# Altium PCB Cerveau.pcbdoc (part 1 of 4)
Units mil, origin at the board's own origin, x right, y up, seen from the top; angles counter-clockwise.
Board outline 3985.6 x 3546.5 mil, 2 copper layers (Top Layer, Bottom Layer), stack 62.2 mil thick; 170 components, 173 nets, 734 pads, 576 vias.
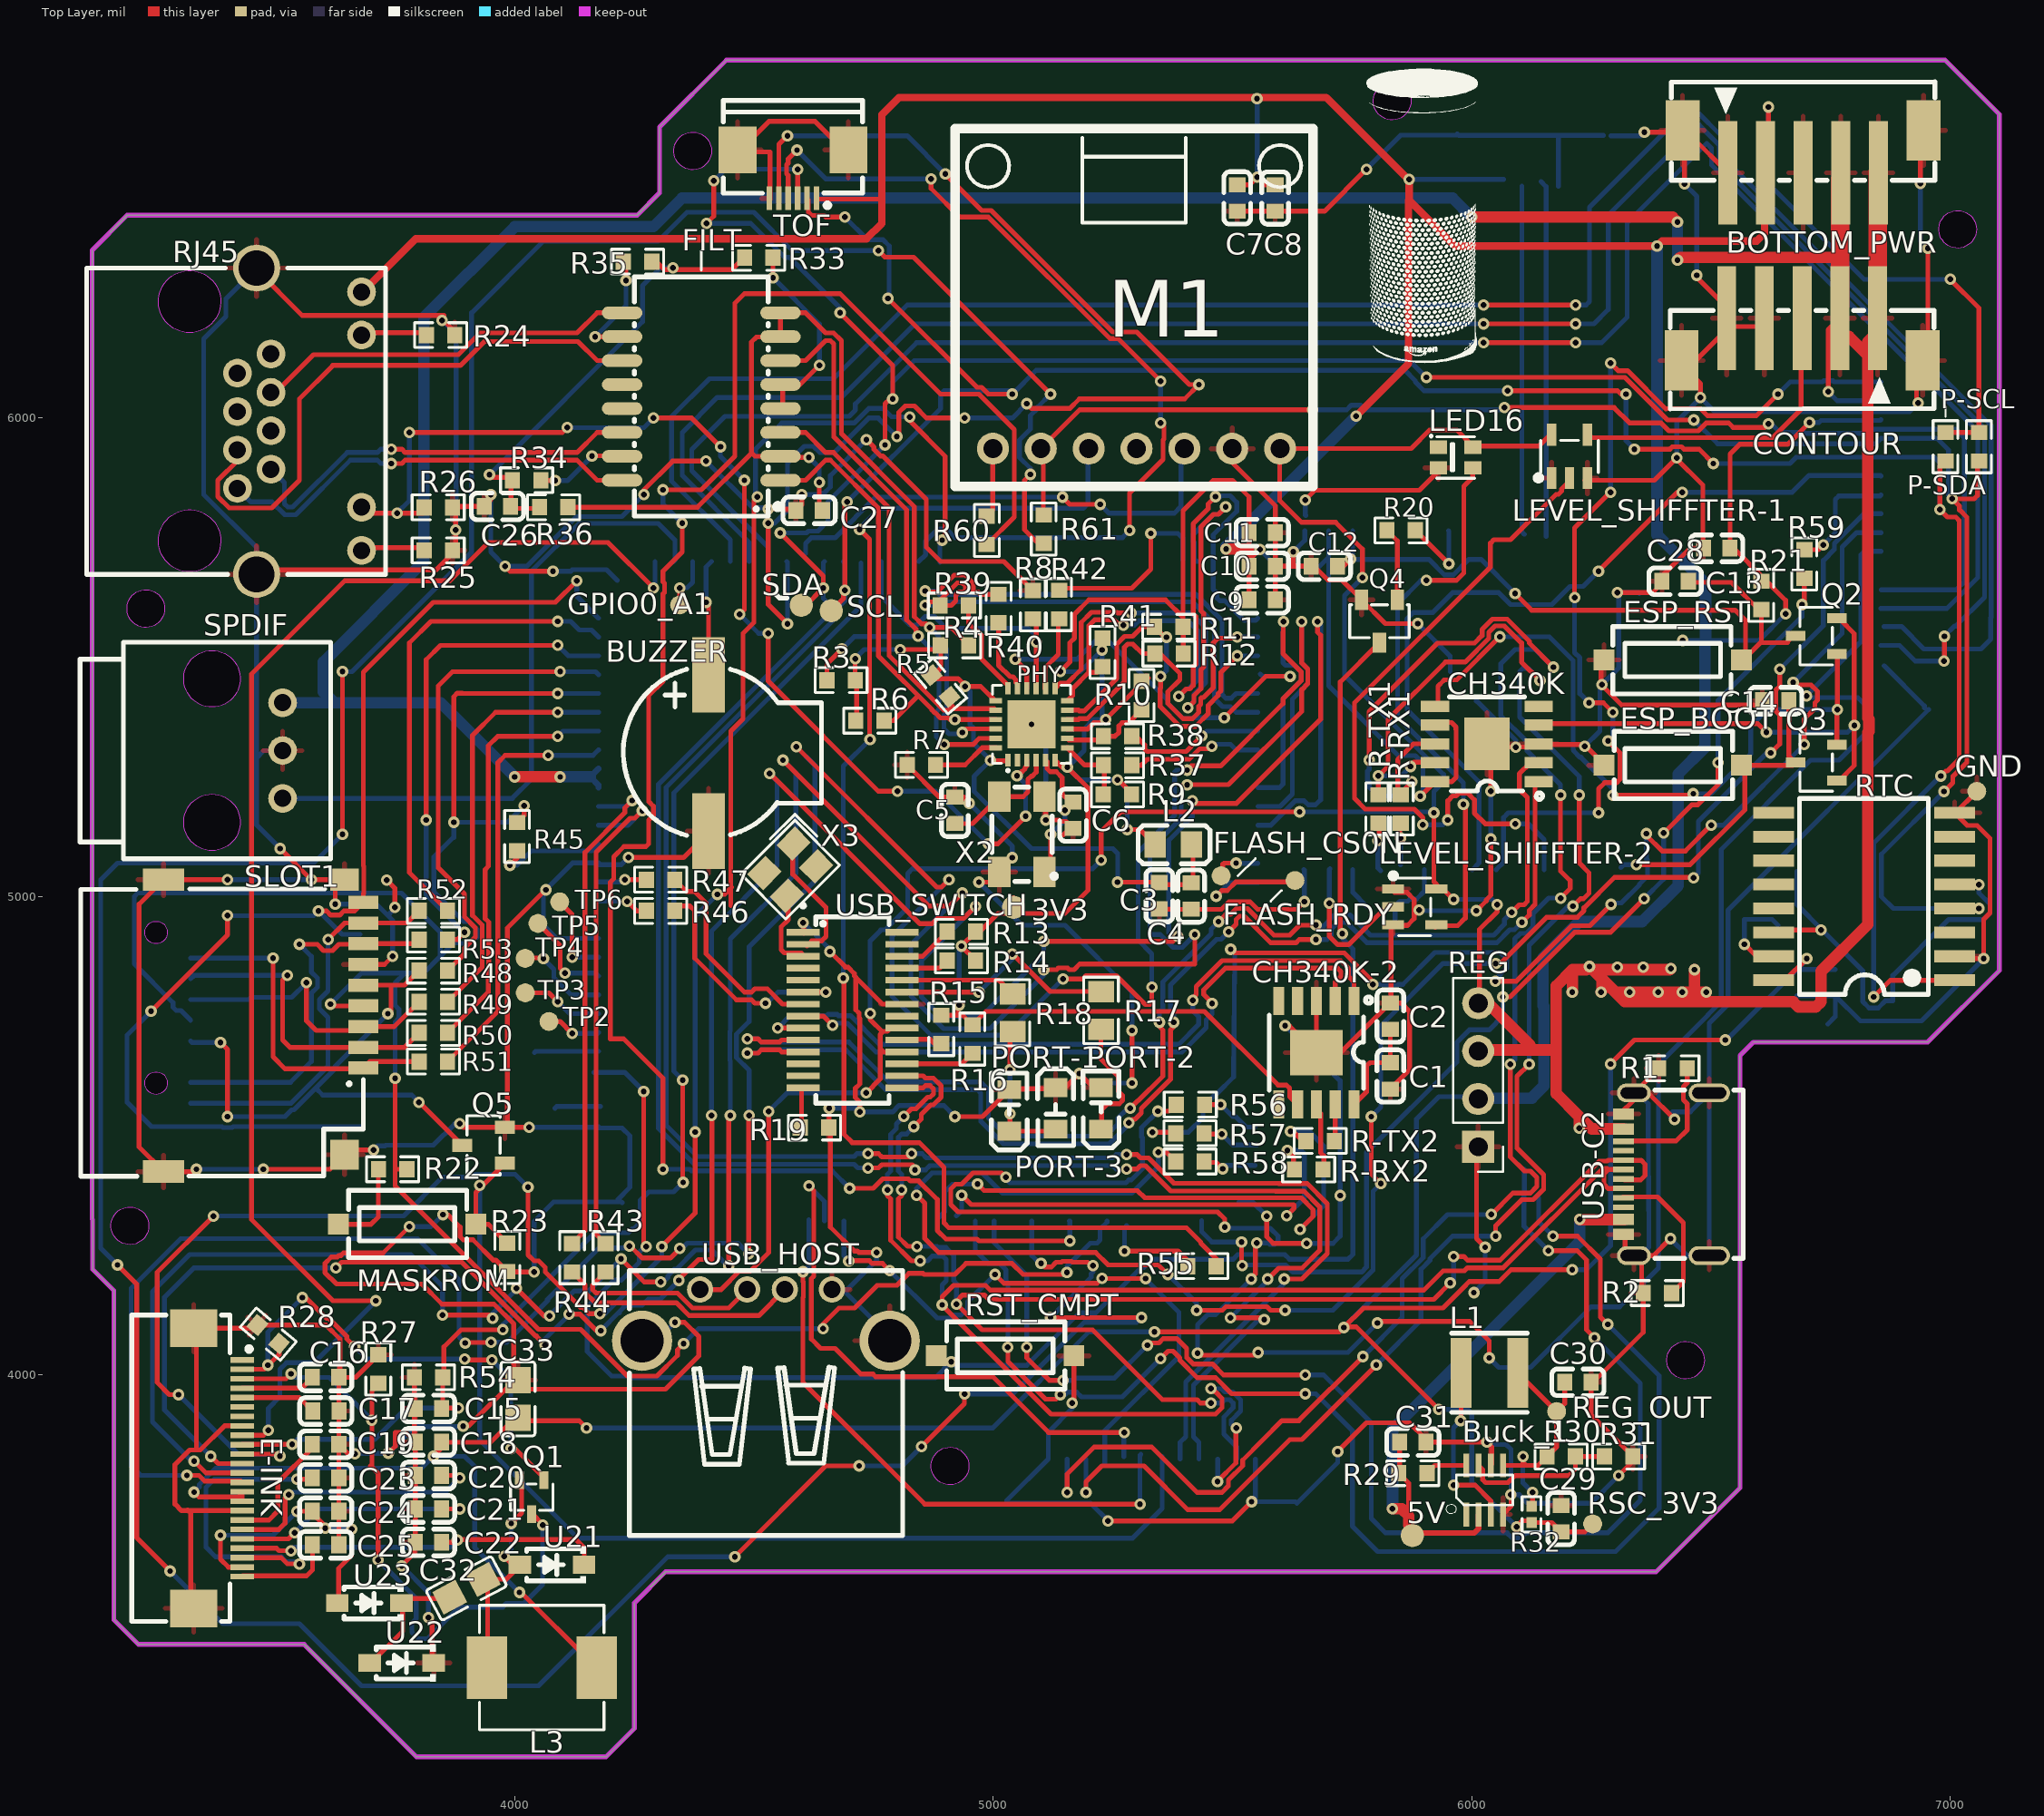
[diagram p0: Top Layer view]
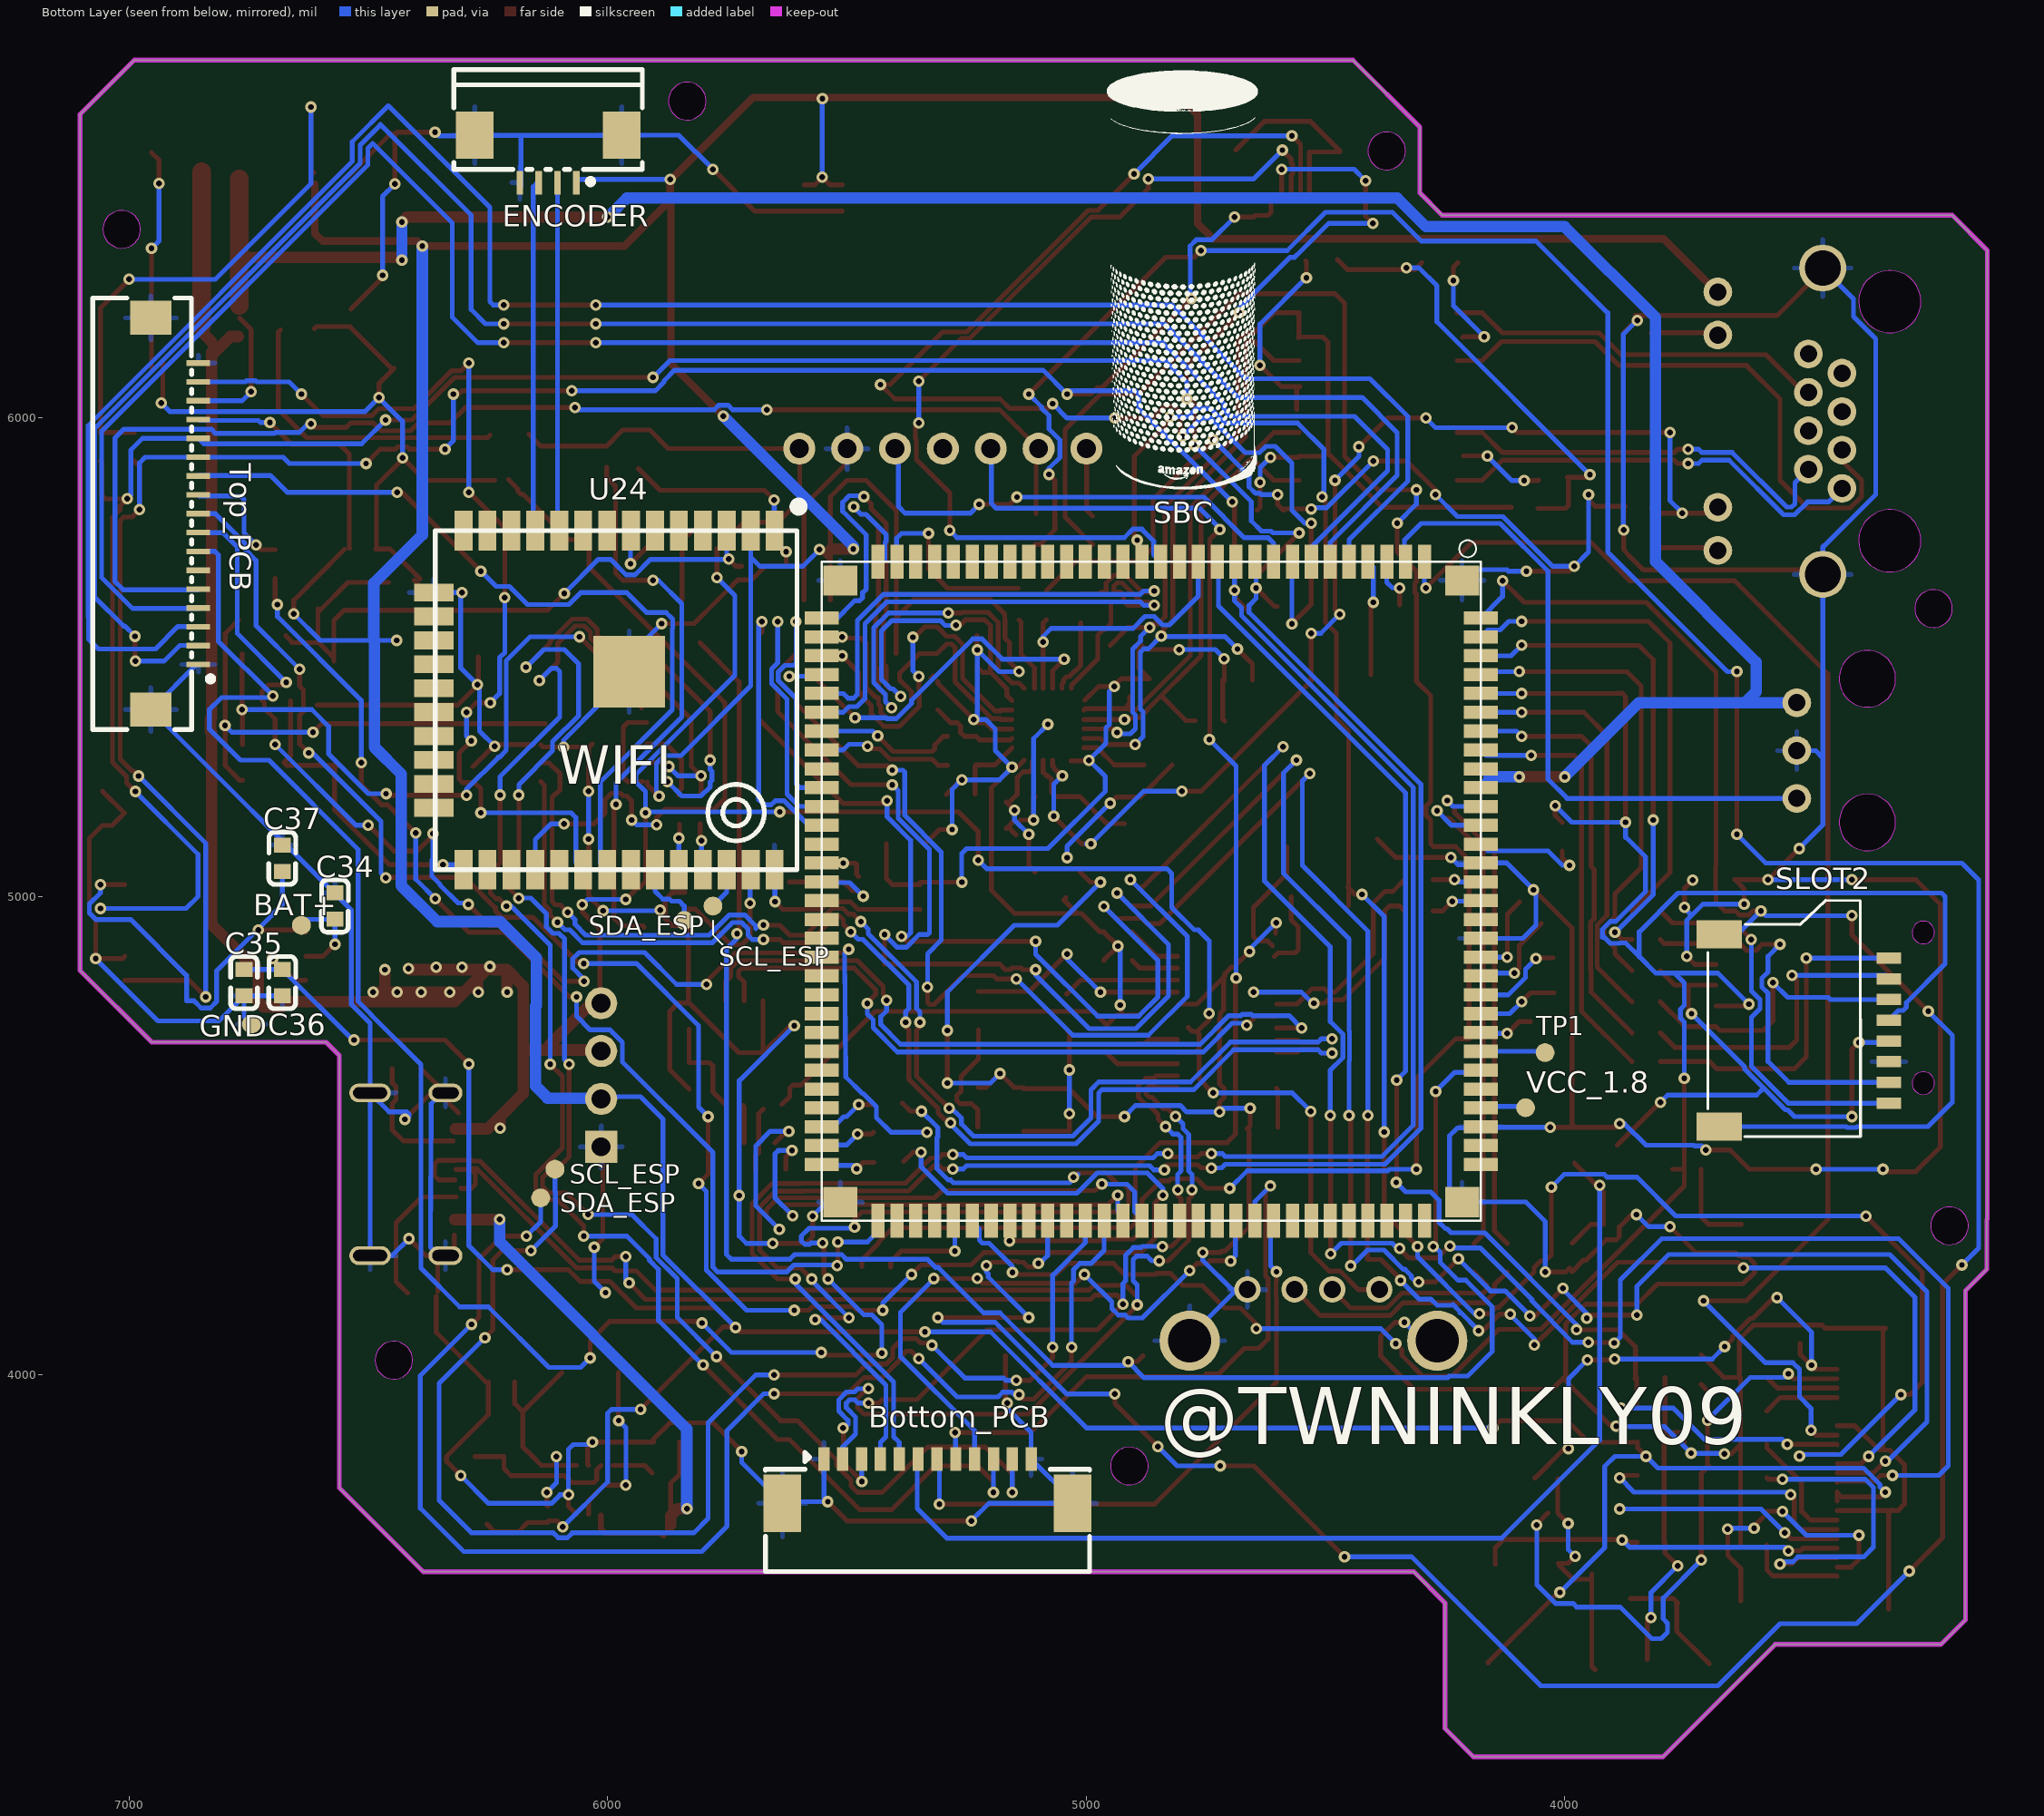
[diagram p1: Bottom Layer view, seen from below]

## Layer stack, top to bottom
Top Solder Mask Layer: solder mask 0.4, Dk 3.3
Top Layer: signal copper 1.4
Dielectric1: surface 59.4, FR4, Dk 4.5
Bottom Layer: signal copper 1.4
Bottom Solder Mask Layer: solder mask 0.4, Dk 3.3

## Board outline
3116.9,4325.7 3116.9,6350.7 3190.2,6424 4256,6424 4302.6,6470.6 4302.6,6608.3 4442.5,6748.1 6989.2,6748.1 7102.5,6634.9 7102.5,4845.3 6952.6,4695.4 6588.4,4695.4 6560.7,4667.7 6560.7,3764 6385.3,3588.6 4315.4,3588.6 4250.4,3523.6 4250.4,3261.6 4190.5,3201.6 3795.2,3201.6 3559.9,3437 3213.5,3437 3162.4,3488.1 3162.4,4176.4 3118,4220.8 3118,4324.6
cut-out: 4411.3,6558.4 4410.9,6552.9 4409.7,6547.5 4407.8,6542.4 4405.3,6537.5 4402,6533.1 4398.2,6529.1 4393.9,6525.8 4389.1,6523 4384,6520.9 4378.7,6519.6 4373.3,6519 4367.8,6519.2 4362.4,6520.2 4357.1,6521.9 4352.2,6524.3 4347.6,6527.4 4343.6,6531 4340,6535.3 4337.1,6539.9 4334.9,6544.9 4333.4,6550.2 4332.6,6555.6 4332.6,6561.1 4333.4,6566.6 4334.9,6571.9 4337.1,6576.9 4340,6581.5 4343.6,6585.7 4347.6,6589.4 4352.2,6592.5 4357.1,6594.9 4362.4,6596.6 4367.8,6597.5 4373.3,6597.7 4378.7,6597.2 4384,6595.8 4389.1,6593.8 4393.9,6591 4398.2,6587.6 4402,6583.7 4405.3,6579.3 4407.8,6574.4 4409.7,6569.2 4410.9,6563.9
cut-out: 3235.1,4311.8 3234.7,4306.3 3233.6,4301 3231.7,4295.8 3229.1,4290.9 3225.9,4286.5 3222.1,4282.6 3217.8,4279.2 3213,4276.4 3207.9,4274.4 3202.6,4273 3197.1,4272.5 3191.6,4272.7 3186.2,4273.6 3181,4275.3 3176.1,4277.7 3171.5,4280.8 3167.4,4284.5 3163.9,4288.7 3161,4293.3 3158.8,4298.3 3157.2,4303.6 3156.5,4309.1 3156.5,4314.6 3157.2,4320 3158.8,4325.3 3161,4330.3 3163.9,4335 3167.4,4339.2 3171.5,4342.8 3176.1,4345.9 3181,4348.3 3186.2,4350 3191.6,4351 3197.1,4351.2 3202.6,4350.6 3207.9,4349.3 3213,4347.2 3217.8,4344.4 3222.1,4341.1 3225.9,4337.1 3229.1,4332.7 3231.7,4327.8 3233.6,4322.7 3234.7,4317.3
cut-out: 4949,3809.6 4948.6,3804.1 4947.4,3798.7 4945.6,3793.6 4943,3788.7 4939.7,3784.3 4935.9,3780.3 4931.6,3776.9 4926.8,3774.2 4921.8,3772.1 4916.4,3770.8 4911,3770.2 4905.5,3770.4 4900.1,3771.4 4894.8,3773.1 4889.9,3775.5 4885.3,3778.6 4881.3,3782.2 4877.7,3786.4 4874.8,3791.1 4872.6,3796.1 4871.1,3801.4 4870.3,3806.8 4870.3,3812.3 4871.1,3817.8 4872.6,3823 4874.8,3828.1 4877.7,3832.7 4881.3,3836.9 4885.3,3840.6 4889.9,3843.7 4894.8,3846.1 4900.1,3847.8 4905.5,3848.7 4911,3848.9 4916.4,3848.3 4921.8,3847 4926.8,3845 4931.6,3842.2 4935.9,3838.8 4939.7,3834.9 4943,3830.4 4945.6,3825.6 4947.4,3820.4 4948.6,3815.1
cut-out: 6486.3,4030.8 6485.9,4025.3 6484.8,4019.9 6482.9,4014.8 6480.3,4009.9 6477.1,4005.5 6473.3,4001.5 6468.9,3998.1 6464.2,3995.4 6459.1,3993.3 6453.8,3992 6448.3,3991.4 6442.8,3991.6 6437.4,3992.6 6432.2,3994.3 6427.2,3996.7 6422.7,3999.8 6418.6,4003.4 6415.1,4007.6 6412.2,4012.3 6409.9,4017.3 6408.4,4022.6 6407.6,4028 6407.6,4033.5 6408.4,4039 6409.9,4044.3 6412.2,4049.3 6415.1,4053.9 6418.6,4058.1 6422.7,4061.8 6427.2,4064.9 6432.2,4067.3 6437.4,4069 6442.8,4069.9 6448.3,4070.1 6453.8,4069.6 6459.1,4068.2 6464.2,4066.2 6468.9,4063.4 6473.3,4060 6477.1,4056.1 6480.3,4051.6 6482.9,4046.8 6484.8,4041.6 6485.9,4036.3
cut-out: 7054.9,6394.5 7054.5,6389 7053.3,6383.6 7051.5,6378.5 7048.9,6373.6 7045.7,6369.2 7041.8,6365.2 7037.5,6361.9 7032.8,6359.1 7027.7,6357.1 7022.3,6355.7 7016.9,6355.2 7011.4,6355.3 7006,6356.3 7000.7,6358 6995.8,6360.4 6991.3,6363.5 6987.2,6367.1 6983.6,6371.4 6980.7,6376 6978.5,6381 6977,6386.3 6976.2,6391.8 6976.2,6397.2 6977,6402.7 6978.5,6408 6980.7,6413 6983.6,6417.6 6987.2,6421.8 6991.3,6425.5 6995.8,6428.6 7000.7,6431 7006,6432.7 7011.4,6433.7 7016.9,6433.8 7022.3,6433.3 7027.7,6431.9 7032.8,6429.9 7037.5,6427.1 7041.8,6423.8 7045.7,6419.8 7048.9,6415.4 7051.5,6410.5 7053.3,6405.3 7054.5,6400
cut-out: 5872.9,6662.5 5872.6,6657 5871.4,6651.6 5869.5,6646.5 5867,6641.6 5863.7,6637.2 5859.9,6633.2 5855.6,6629.9 5850.8,6627.1 5845.7,6625 5840.4,6623.7 5834.9,6623.1 5829.5,6623.3 5824,6624.3 5818.8,6626 5813.9,6628.4 5809.3,6631.5 5805.2,6635.1 5801.7,6639.3 5798.8,6644 5796.6,6649 5795.1,6654.3 5794.3,6659.7 5794.3,6665.2 5795.1,6670.7 5796.6,6676 5798.8,6681 5801.7,6685.6 5805.2,6689.8 5809.3,6693.5 5813.9,6696.6 5818.8,6699 5824,6700.7 5829.5,6701.6 5834.9,6701.8 5840.4,6701.3 5845.7,6699.9 5850.8,6697.9 5855.6,6695.1 5859.9,6691.7 5863.7,6687.8 5867,6683.4 5869.5,6678.5 5871.4,6673.3 5872.6,6668
cut-out: 3268.5,5601.7 3268.1,5596.3 3267,5590.9 3265.1,5585.7 3262.5,5580.9 3259.3,5576.4 3255.5,5572.5 3251.2,5569.1 3246.4,5566.4 3241.3,5564.3 3236,5563 3230.5,5562.4 3225,5562.6 3219.6,5563.5 3214.4,5565.2 3209.5,5567.7 3204.9,5570.7 3200.8,5574.4 3197.3,5578.6 3194.4,5583.3 3192.1,5588.3 3190.6,5593.6 3189.9,5599 3189.9,5604.5 3190.6,5609.9 3192.1,5615.2 3194.4,5620.2 3197.3,5624.9 3200.8,5629.1 3204.9,5632.8 3209.5,5635.8 3214.4,5638.3 3219.6,5640 3225,5640.9 3230.5,5641.1 3236,5640.5 3241.3,5639.2 3246.4,5637.1 3251.2,5634.4 3255.5,5631 3259.3,5627.1 3262.5,5622.6 3265.1,5617.8 3267,5612.6 3268.1,5607.2

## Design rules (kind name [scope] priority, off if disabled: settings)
BoardOutlineClearance copperThickness1oz [All] p0: genericclearance=10 ignorepadtopadclearanceinfootprint=FALSE except(0: Arc-SplitContinuation Track-SplitContinuation SMDPad-SplitContinuation THPad-SplitContinuation Via-SplitContinuation Fill-SplitContinuation Poly-SplitContinuation Region-SplitContinuation Text-SplitContinuation)
BoardOutlineClearance copperThickness2oz [All] p0: genericclearance=10 ignorepadtopadclearanceinfootprint=FALSE except(0: Arc-SplitContinuation Track-SplitContinuation SMDPad-SplitContinuation THPad-SplitContinuation Via-SplitContinuation Fill-SplitContinuation Poly-SplitContinuation Region-SplitContinuation Text-SplitContinuation)
BoardOutlineClearance Plane_innerPlane [All] p0: genericclearance=10 ignorepadtopadclearanceinfootprint=FALSE except(0: Arc-SplitContinuation Track-SplitContinuation SMDPad-SplitContinuation THPad-SplitContinuation Via-SplitContinuation Fill-SplitContinuation Poly-SplitContinuation Region-SplitContinuation Text-SplitContinuation)
BoardOutlineClearance Copper_copperRegion [All] p0: genericclearance=10 ignorepadtopadclearanceinfootprint=FALSE except(0: Arc-SplitContinuation Track-SplitContinuation SMDPad-SplitContinuation THPad-SplitContinuation Via-SplitContinuation Fill-SplitContinuation Poly-SplitContinuation Region-SplitContinuation Text-SplitContinuation)
BoardOutlineClearance otherClearance [All] p0: genericclearance=10 ignorepadtopadclearanceinfootprint=FALSE except(0: Arc-SplitContinuation Track-SplitContinuation SMDPad-SplitContinuation THPad-SplitContinuation Via-SplitContinuation Fill-SplitContinuation Poly-SplitContinuation Region-SplitContinuation Text-SplitContinuation)
Clearance copperThickness1oz [All] p1: gap=7 ignorepadtopadclearanceinfootprint=FALSE
Clearance copperThickness2oz [All] p1: gap=7 ignorepadtopadclearanceinfootprint=FALSE
Clearance Plane_innerPlane [All] p1: gap=7 ignorepadtopadclearanceinfootprint=FALSE
Clearance Copper_copperRegion [All] p1: gap=7 ignorepadtopadclearanceinfootprint=FALSE
Clearance otherClearance [All] p1: gap=7 ignorepadtopadclearanceinfootprint=FALSE
DiffPairsRouting differentialPair [All] p1: maxuncoupledlength=10 minlimit=6 maxlimit=Infinity mostfreqgap=6 toplayer_minwidth=5 toplayer_prefwidth=10 toplayer_maxwidth=100 bottomlayer_minwidth=5 bottomlayer_prefwidth=10 bottomlayer_maxwidth=100
PasteMaskExpansion pasteMaskExpansion [All] p1: expansion=0
PlaneConnect innerPlane [All] p1: planeconnectstyle=Relief reliefexpansion=20 reliefentries=4 reliefconductorwidth=10 reliefairgap=10
PolygonConnect copperRegion [All] p1: connectstyle=Relief reliefentries=4 reliefconductorwidth=10 polygonreliefangle="90 Angle" airgapwidth=10
RoutingVias viaSize [All] p1: viastyle="Through Hole" holewidth=12.0078 minholewidth=11.811 maxholewidth=248.0314 width=12.0078 minwidth=11.811 maxwidth=248.0314
SolderMaskExpansion solderMaskExpansion [IsVia] p1: useseparateexpansions=TRUE expansion=-1000 expansionbottom=-1000
SolderMaskExpansion solderMaskExpansion [All] p2: useseparateexpansions=TRUE expansion=2 expansionbottom=2
Width copperThickness1oz [All] p1: maxlimit=100 minlimit=5 preferedwidth=10
Width copperThickness2oz [All] p1: maxlimit=100 minlimit=8 preferedwidth=10

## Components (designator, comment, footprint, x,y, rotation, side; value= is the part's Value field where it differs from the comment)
3V3 "" Test-Point-0.5mm#1 5042.7,4977.2 r0 top
5V "" Test-Point-0.5mm#1 5876.1,3664.6 r0 top
BAT+ "" Test-Point-0.5mm#2 6640,4940 r180 bottom
Bottom_PCB "FPC-1.0FX-12PWBH20" FPC-SMD_12P-P1.00_XUNPU_FPC-1.0FX-12PWBH20 5331.5,3778 r180 bottom
BOTTOM_PWR "B5B-PH-SM4-TB(LF)(SN)" CONN-SMD_5P-P2.00_B6B-PH-SM4-TB-LF-SN#1 6692.6,6556.8 r180 top locked
Buck_1 "IC-new_PMIC-MP2161_'GJ'" TSOT23-8 6026.9,3759.6 r0 top
BUZZER "MLT-9032" BUZ-SMD_MLT-9032 4405,5300 r90 top locked
C1 "100nF" C0603#1 5830,4625 r90 top
C2 "100nF" C0603#1 5830,4750 r90 top
C3 "1uF" C0603#2 5347.2,5001.5 r270 top
C4 "1uF" C0603#3 5413.8,5000.8 r90 top
C5 "22pF" C0603#1 4920,5180 r270 top
C6 "22pF" C0603#1 5166.7,5170 r270 top
C7 "1uF" C0603#1 5510,6460 r270 top
C8 "1uF" C0603#2 5589.2,6459.9 r90 top
C9 "22uF" C0603#3 5562.2,5620.3 r0 top locked
C10 "100nF" C0603#2 5562.2,5690.3 r180 top locked
C11 "100nF" C0603#3 5562.2,5760.3 r0 top locked
C12 "1uF" C0603#2 5692.2,5690.3 r180 top locked
C13 "100nF" C0603#2 6425.1,5658.9 r180 top
C14 "100nF" C0603#2 6635,5409.3 r0 top
C15 "100nF" C0603#1 3820,3930 r0 top
C16 "1uF" C0603#1 3605,3995 r180 top
C17 "1uF" C0603#2 3605.3,3924.7 r180 top
C18 "100nF" C0603#1 3820,3860 r0 top
C19 "1uF" C0603#1 3605,3855 r0 top
C20 "1uF" C0603#1 3820,3790 r180 top
C21 "1uF" C0603#1 3820,3720 r180 top
C22 "1uF" C0603#1 3820,3650 r180 top
C23 "1uF" C0603#1 3605,3785 r0 top
C24 "1uF" C0603#1 3605,3715 r0 top
C25 "1uF" C0603#1 3605,3645 r0 top
C26 "1nF" C0603#1 3964,5815.5 r0 top
C27 "10nF" C0603#1 4615.4,5807.1 r0 top
C28 "100nF" C0603#2 6511.7,5727.9 r180 top
C29 "100nF" C0603#3 6186.9,3699.6 r270 top
C30 "10uF" C0603#3 6221.9,3984.6 r0 top
C31 "10uF" C0603#3 5876.9,3859.6 r0 top
C32 "4.7uF" C0805 3899.1,3554.1 r28 top
C33 "4.7uF" C0805 4006.9,3949.9 r270 top
C34 "100nF" C0603#1 6570,4980 r90 bottom
C35 "100nF" C0603#1 6760,4820 r270 bottom
C36 "6.8uF" C0603#1 6680,4820 r90 bottom
C37 "100nF" C0603#1 6680,5080 r90 bottom
CH340K "CH340K" ESOP-10_L4.9-W3.9-P1.00-LS6.2-BL-EP 6031.7,5318.8 r90 top locked
CH340K-2 "CH340K" ESOP-10_L4.9-W3.9-P1.00-LS6.2-BL-EP 5675.4,4673.6 r180 top locked
CONTOUR "B5B-PH-SM4-TB(LF)(SN)" CONN-SMD_5P-P2.00_B6B-PH-SM4-TB-LF-SN#2 6690.5,6164.6 r0 top locked
E-INK "FPC-05F-24PH20" FPC-SMD_24P-P0.50_FPC-05F-24PH20 3380,3805 r270 top locked
ENCODER "AFA01-S04FCA-00" FPC-SMD_4P-P1.00_JS_AFA01-S04FCA-00 6124.5,6541.7 r0 bottom locked
ESP_BOOT "HX 3x6x2.5A-2.5N" SW-SMD_HX-TS-1101-C-W 6420,5274.3 r0 top
ESP_RST "HX 3x6x2.5A-2.5N" SW-SMD_HX-TS-1101-C-W 6420,5494.3 r180 top
FILT "HX1188NL" XFMR-SMD_16P-L12.7-W7.1-P1.27-LS9.4-BL 4390,6045 r90 top locked
FLASH_CS0N "" Test-Point-0.5mm#2 5476.4,5043.2 r0 top
FLASH_RDY "" Test-Point-0.5mm#2 5630.7,5033.5 r0 top
GND "" Test-Point-0.5mm#2 7055.5,5219.9 r0 top
GPIO0_A1 "" Test-Point-0.5mm#2 4344.7,5609.4 r0 top
L1 "1uH" IND-SMD_L4.0-W4.0_ANR4012 6036.9,4004.6 r0 top
L2 "MPZ2012S601AT000" L0805 5376.4,5108.6 r180 top
L3 "68uH" IND-SMD_L7.1-W6.6_H5.0 4056.7,3388.5 r180 top
LED16 "WS2812B-2020" LED-SMD_4P-L2.0-W2.0-TL_WS2812B-2020 5966.6,5917.4 r0 top
LEVEL_SHIFFTER-1 "74AHCT1G125GV" SOT-23-5_L3.0-W1.7-P0.95-LS2.8-BL 6204.4,5919.8 r0 top
LEVEL_SHIFFTER-2 "74AHCT1G125GV" SOT-23-5_L3.0-W1.7-P0.95-LS2.8-BL 5881.1,4978.3 r270 top
M1 "LD_MAX98357_Module" LD:MAX98357_Module 5599.5,5936 r270 top locked
MASKROM "HX 3x6x2.5A-2.5N" SW-SMD_HX-TS-1101-C-W 3775,4315 r0 top
P-SCL "2.2kΩ" R0603#1 6990,5940 r90 top
P-SDA "2.2kΩ" R0603#1 7060,5940 r90 top
PHY "LAN8720AI-CP" QFN-24_L4.0-W4.0-P0.50-BL-EP2.6 5080,5360 r0 top locked
PORT-1 "YLED0805Y" LED0805-RD_YELLOW 5033.5,4552.8 r90 top
PORT-2 "YLED0805Y" LED0805-RD_YELLOW 5225.5,4557.1 r90 top
PORT-3 "YLED0805Y" LED0805-RD_YELLOW 5130.5,4557.1 r270 top
Q1 "SI1308EDL" SOT-323-3_L2.0-W1.3-P1.30-LS2.1-BR 4035.5,3744.7 r90 top
Q2 "BSS138" SOT-23-3_L3.0-W1.7-P0.95-LS2.9-BR#1 6720,5544.3 r0 top
Q3 "BSS138" SOT-23-3_L3.0-W1.7-P0.95-LS2.9-BR#2 6720,5280 r0 top
Q4 "MMBT3904" TSOT-23-3_L3.0-W1.6-P0.95-LS2.8-BR#1 5807.2,5575.3 r90 top locked
Q5 "MMBT3904" TSOT-23-3_L3.0-W1.6-P0.95-LS2.8-BR#2 3935,4480 r0 top
R1 "5.1kΩ" R0603_1#1 6420.5,4640.9 r0 top
R2 "5.1kΩ" R0603_1#2 6387.8,4171.1 r0 top
R3 "49.9Ω" R0603#1 4682.1,5452.2 r180 top
R4 "49.9Ω" R0603#1 4919.2,5524.7 r0 top
R5 "49.9Ω" R0603#1 4890,5440 r130 top
R6 "49.9Ω" R0603#2 4742.4,5367.6 r180 top
R7 "12.1kΩ" R0603#1 4850,5275 r0 top
R8 "10kΩ" R0603#1 5082.9,5609.8 r90 top
R9 "10kΩ" R0603#2 5259.7,5213.4 r180 top
R10 "10kΩ" R0603#1 5310,5420 r270 top
R11 "10kΩ" R0603#2 5366.8,5563.8 r0 top
R12 "10kΩ" R0603#3 5367.4,5507.8 r0 top
R13 "10kΩ" R0603#1 4933.5,4926.3 r0 top
R14 "10kΩ" R0603#1 4933.5,4866.3 r0 top
R15 "10kΩ" R0603#1 4891.5,4722 r90 top
R16 "10kΩ" R0603#1 4956.5,4702 r90 top
R17 "260Ω" R0805#1 5225.5,4762.1 r90 top
R18 "260Ω" R0805#2 5040.5,4757.1 r270 top
R19 "2.7kΩ" R0603#2 4626.5,4517 r180 top
R20 "100Ω" R0603#2 5852.2,5765.3 r0 top locked
R21 "10kΩ" R0603#1 6605,5629.3 r90 top
R22 "10kΩ" R0603#1 3745,4430 r0 top
R23 "100kΩ" R0603#1 3984.6,4245.7 r270 top
R24 "220Ω" R0603#2 3845.3,6173.4 r180 top
R25 "270Ω" R0603#3 3840.3,5723.4 r0 top
R26 "10kΩ" R0603#3 3840.3,5813.4 r0 top
R27 "10kΩ" R0603#1 3715,4012.4 r90 top
R28 "10kΩ" R0603#1 3485,4085 r320 top
R29 "100kΩ" R0603#2 5876.9,3794.6 r0 top
R30 "200kΩ" R0603#3 6186.9,3829.6 r180 top
R31 "44.2kΩ" R0603#2 6306.9,3829.6 r0 top
R32 "0Ω" R0402 6125.1,3708.5 r270 top
R33 "75Ω" R0603#1 4510,6335 r180 top
R34 "75Ω" R0603#1 4025,5870 r180 top
R35 "75Ω" R0603#1 4256.8,6327 r0 top
R36 "75Ω" R0603#1 4081.6,5813.6 r180 top
R37 "22Ω" R0603#1 5260,5274.3 r180 top
R38 "22Ω" R0603#1 5260,5335 r180 top
R39 "22Ω" R0603#2 4918.8,5608.3 r0 top
R40 "22Ω" R0603#3 5011.2,5601.8 r270 top
R41 "1.5kΩ" R0603#3 5228.4,5510.2 r90 top
R42 "22Ω" R0603#1 5137.7,5610.1 r270 top
R43 "22Ω" R0603#1 4190,4245 r270 top
R44 "22Ω" R0603#1 4120,4245 r270 top
R45 "100kΩ" R0603#1 4005,5125 r90 top
R46 "22Ω" R0603#1 4305,4970 r0 top
R47 "22Ω" R0603#1 4305,5035 r0 top
R48 "22Ω" R0603#1 3830,4845 r180 top
R49 "22Ω" R0603#1 3830,4780 r180 top
R50 "22Ω" R0603#1 3830,4715 r180 top
R51 "22Ω" R0603#1 3830,4655 r180 top
R52 "22Ω" R0603#1 3830,4970 r180 top
R53 "22Ω" R0603#1 3830,4910 r180 top
R54 "10kΩ" R0603#1 3820,3995 r0 top
R55 "22Ω" R0603#2 5436.3,4227.3 r0 top
R56 "22Ω" R0603#2 5412,4564.9 r180 top
R57 "22Ω" R0603#3 5411.3,4505.1 r180 top
R58 "22Ω" R0603#2 5411.2,4445.9 r180 top
R59 "22Ω" R0603#1 6695,5695 r90 top
R60 "22Ω" R0603#3 4986.6,5765.4 r90 top
R61 "22Ω" R0603#3 5105.5,5767.7 r90 top
R-RX1 "1kΩ" R0603_1#2 5851.6,5182.9 r270 top locked
R-RX2 "1kΩ" R0603_1#1 5659.3,4429.4 r180 top
R-TX1 "1kΩ" R0603_1#2 5804.8,5182.9 r270 top locked
R-TX2 "1kΩ" R0603_1#1 5683.2,4489.1 r180 top
REG "Connector_Conn_01x04_Male" Connector_PinHeader_2.54mm:PinHeader_1x04_P2.54mm_Vertical 6013.6,4476.9 r180 top
REG_OUT "" Test-Point-0.5mm#2 6177.5,3923.6 r0 top
RJ45 "R-RJ45R08P-C000" RJ45-TH_R-RJ45R08P-C000 3550.3,5993.4 r270 top locked
RSC_3V3 "" Test-Point-0.5mm#2 6252.7,3688.6 r0 top
RST_CMPT "HX 3x6x2.5A-2.5N" SW-SMD_HX-TS-1101-C-W 5025,4040 r0 top locked
RTC "PCF2129T/2,518" SO-16_L10.3-W7.5-P1.27-LS10.3-BL 6820,5000 r90 top
SBC "Radxa_rCore_RK3308" Radxa_rCore_RK3308-bon_1 4175,5700 r270 bottom locked
SCL "" Test-Point-0.5mm#1 4661.6,5597.3 r0 top
SDA "" Test-Point-0.5mm#1 4598.9,5608.9 r0 top
SLOT1 "TF PUSH" TF-SMD_TF-PUSH 3475,4730 r270 top locked
SLOT2 "" TF-SMD_TF-025 3555,4720 r90 bottom locked
SPDIF "DLR2180" CONN-TH_DLR2180_1 3515,5305 r270 top locked
TOF "FPC-05F-6PH20" FPC-SMD_6P-P0.50_XUNPU_FPC-05F-6PH20 4581.6,6509.8 r180 top
Top_PCB "ZX-1.0FPC-2H-QFX17P" FPC-SMD_17P-P1.00_ZX-1.0FPC-2H-QFX17P 6905,5800 r270 bottom
TP1 "" Test-Point-0.5mm#2 4041,4673.7 r180 bottom
TP2 "" Test-Point-0.5mm#2 4071.6,4738.7 r0 top
TP3 "" Test-Point-0.5mm#2 4022.2,4798.7 r0 top
TP4 "" Test-Point-0.5mm#2 4021.9,4870.7 r0 top
TP5 "" Test-Point-0.5mm#2 4048.5,4943.7 r0 top
TP6 "" Test-Point-0.5mm#2 4094.1,4988.7 r0 top
U21 "MBR0530" SOD-123_L2.7-W1.6-LS3.7-RD-1#1 4078,3603.1 r180 top
U22 "MBR0530" SOD-123_L2.7-W1.6-LS3.7-RD-1#2 3764,3398 r180 top
U23 "MBR0530" SOD-123_L2.7-W1.6-LS3.7-RD-1#2 3696.2,3523.3 r180 top
U24 "2.4GHz" WIFIM-SMD_38P-L19.2-W18.0-P1.27 6007.2,5410.3 r180 bottom locked
USB-C2 "UC.01.51-11-0017,typec" TYPE-C-SMD_UC.01.51-11-0017 6406.7,4419.4 r90 top
USB_HOST "UE27AC54100" USB-A-TH_UE27AC54100 4525,4125 r0 top locked
USB_SWITCH "FE1.1S-BSOP28BCN" SSOP-28_L9.9-W3.9-P0.635-LS6.0-BL-1 4705.8,4762.6 r270 top locked
VCC_1.8 "" Test-Point-0.5mm#2 4081.7,4558.5 r180 bottom
X2 "25MHz" CRYSTAL-SMD_4P-L5.0-W3.2-BL 5060,5130 r90 top
X3 "12MHz" CRYSTAL-SMD_4P-L3.2-W2.5-BL 4576,5056.1 r225 top

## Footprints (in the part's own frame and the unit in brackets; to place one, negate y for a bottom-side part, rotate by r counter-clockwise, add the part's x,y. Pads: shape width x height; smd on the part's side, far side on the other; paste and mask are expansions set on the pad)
BUZ-SMD_MLT-9032 [mil]
  rect 157.5x68.9 smd paste+0 mask+2: 1(163.4,0) 2(-163.4,0)
  silkscreen extent -172,-236 175,178
C0603#1 [mil]
  rect 31.5x35.4 smd: 1(-27.6,0) 2(27.6,0)
  silkscreen extent -55,-28 55,28
C0603#2 [mil]
  rect 31.5x35.4 smd: 1(-27.6,0) 2(27.5,0)
  silkscreen extent -55,-28 55,28
C0603#3 [mil]
  rect 31.5x35.4 smd: 1(-27.5,0) 2(27.6,0)
  silkscreen extent -55,-28 55,28
C0805 [mil]
  rect 55.5x53.1 smd paste-3937 mask+2: 1(-39.41,0) 2(39.41,0)
  silkscreen extent -77,-36 77,36
CONN-SMD_5P-P2.00_B6B-PH-SM4-TB-LF-SN#1 [mil]
  rect 39.4x216.5 smd: 1(157.5,44.2) 2(78.8,44.2) 3(0,44.2) 4(-78.7,44.2) 5(-157.4,44.2)
  rect 70.9x126 smd: 6(252,-44.3) 7(-251.9,-44.3)
  silkscreen extent -276,-146 276,60
CONN-SMD_5P-P2.00_B6B-PH-SM4-TB-LF-SN#2 [mil]
  rect 39.4x216.5 smd: 1(157.5,44.3) 2(78.7,44.3) 3(0,44.3) 4(-78.8,44.3) 5(-157.5,44.3)
  rect 70.9x126 smd: 6(252,-44.3) 7(-252,-44.3)
  silkscreen extent -276,-146 276,60
CONN-TH_DLR2180_1 [mil]
  round 60 hole 36: 1(100,0) 2(0,0) 3(-100,0)
  Board Outline Layer lines w0.1: 153.4,-206.6 160.3,-205.8 166.9,-204.2 173.4,-201.9 179.5,-198.8 185.3,-195 190.5,-190.6 195.2,-185.6 199.3,-180.1 202.8,-174.1 205.5,-167.8 207.5,-161.3 208.7,-154.5 209.1,-147.6 208.7,-140.8 207.5,-134 205.5,-127.4 202.8,-121.1 199.3,-115.2 195.2,-109.7 190.5,-104.7 185.3,-100.3 179.5,-96.5 173.4,-93.4 166.9,-91.1 160.3,-89.5 153.4,-88.7 146.6,-88.7 139.7,-89.5 133.1,-91.1 126.6,-93.4 120.5,-96.5 114.7,-100.3 109.5,-104.7 104.8,-109.7 100.7,-115.2 97.2,-121.1 94.5,-127.4 92.5,-134 91.3,-140.8 90.9,-147.6 91.3,-154.5 92.5,-161.3 94.5,-167.8 97.2,-174.1 100.7,-180.1 104.8,-185.6 109.5,-190.6 114.7,-195 120.5,-198.8 126.6,-201.9 133.1,-204.2 139.7,-205.8 146.6,-206.6 153.4,-206.6 ; -146.6,-206.6 -139.7,-205.8 -133.1,-204.2 -126.6,-201.9 -120.5,-198.8 -114.7,-195 -109.5,-190.6 -104.8,-185.6 -100.7,-180.1 -97.2,-174.1 -94.5,-167.8 -92.5,-161.3 -91.3,-154.5 -90.9,-147.6 -91.3,-140.8 -92.5,-134 -94.5,-127.4 -97.2,-121.1 -100.7,-115.2 -104.8,-109.7 -109.5,-104.7 -114.7,-100.3 -120.5,-96.5 -126.6,-93.4 -133.1,-91.1 -139.7,-89.5 -146.6,-88.7 -153.4,-88.7 -160.3,-89.5 -166.9,-91.1 -173.4,-93.4 -179.5,-96.5 -185.3,-100.3 -190.5,-104.7 -195.2,-109.7 -199.3,-115.2 -202.8,-121.1 -205.5,-127.4 -207.5,-134 -208.7,-140.8 -209.1,-147.6 -208.7,-154.5 -207.5,-161.3 -205.5,-167.8 -202.8,-174.1 -199.3,-180.1 -195.2,-185.6 -190.5,-190.6 -185.3,-195 -179.5,-198.8 -173.4,-201.9 -166.9,-204.2 -160.3,-205.8 -153.4,-206.6 -146.6,-206.6
  Board Outline Layer region: -90.9,-147.6 -91.3,-154.5 -92.5,-161.3 -94.5,-167.8 -97.2,-174.1 -100.7,-180.1 -104.8,-185.6 -109.5,-190.6 -114.7,-195 -120.5,-198.8 -126.6,-201.9 -133.1,-204.2 -139.7,-205.8 -146.6,-206.6 -153.4,-206.6 -160.3,-205.8 -166.9,-204.2 -173.4,-201.9 -179.5,-198.8 -185.3,-195 -190.5,-190.6 -195.2,-185.6 -199.3,-180.1 -202.8,-174.1 -205.5,-167.8 -207.5,-161.3 -208.7,-154.5 -209.1,-147.6 -208.7,-140.8 -207.5,-134 -205.5,-127.4 -202.8,-121.1 -199.3,-115.2 -195.2,-109.7 -190.5,-104.7 -185.3,-100.3 -179.5,-96.5 -173.4,-93.4 -166.9,-91.1 -160.3,-89.5 -153.4,-88.7 -146.6,-88.7 -139.7,-89.5 -133.1,-91.1 -126.6,-93.4 -120.5,-96.5 -114.7,-100.3 -109.5,-104.7 -104.8,-109.7 -100.7,-115.2 -97.2,-121.1 -94.5,-127.4 -92.5,-134 -91.3,-140.8
  Board Outline Layer region: -90.9,-147.6 -91.3,-154.5 -92.5,-161.3 -94.5,-167.8 -97.2,-174.1 -100.7,-180.1 -104.8,-185.6 -109.5,-190.6 -114.7,-195 -120.5,-198.8 -126.6,-201.9 -133.1,-204.2 -139.7,-205.8 -146.6,-206.6 -153.4,-206.6 -160.3,-205.8 -166.9,-204.2 -173.4,-201.9 -179.5,-198.8 -185.3,-195 -190.5,-190.6 -195.2,-185.6 -199.3,-180.1 -202.8,-174.1 -205.5,-167.8 -207.5,-161.3 -208.7,-154.5 -209.1,-147.6 -208.7,-140.8 -207.5,-134 -205.5,-127.4 -202.8,-121.1 -199.3,-115.2 -195.2,-109.7 -190.5,-104.7 -185.3,-100.3 -179.5,-96.5 -173.4,-93.4 -166.9,-91.1 -160.3,-89.5 -153.4,-88.7 -146.6,-88.7 -139.7,-89.5 -133.1,-91.1 -126.6,-93.4 -120.5,-96.5 -114.7,-100.3 -109.5,-104.7 -104.8,-109.7 -100.7,-115.2 -97.2,-121.1 -94.5,-127.4 -92.5,-134 -91.3,-140.8
  Board Outline Layer region: 209.1,-147.6 208.7,-154.5 207.5,-161.3 205.5,-167.8 202.8,-174.1 199.3,-180.1 195.2,-185.6 190.5,-190.6 185.3,-195 179.5,-198.8 173.4,-201.9 166.9,-204.2 160.3,-205.8 153.4,-206.6 146.6,-206.6 139.7,-205.8 133.1,-204.2 126.6,-201.9 120.5,-198.8 114.7,-195 109.5,-190.6 104.8,-185.6 100.7,-180.1 97.2,-174.1 94.5,-167.8 92.5,-161.3 91.3,-154.5 90.9,-147.6 91.3,-140.8 92.5,-134 94.5,-127.4 97.2,-121.1 100.7,-115.2 104.8,-109.7 109.5,-104.7 114.7,-100.3 120.5,-96.5 126.6,-93.4 133.1,-91.1 139.7,-89.5 146.6,-88.7 153.4,-88.7 160.3,-89.5 166.9,-91.1 173.4,-93.4 179.5,-96.5 185.3,-100.3 190.5,-104.7 195.2,-109.7 199.3,-115.2 202.8,-121.1 205.5,-127.4 207.5,-134 208.7,-140.8
  Board Outline Layer region: 209.1,-147.6 208.7,-154.5 207.5,-161.3 205.5,-167.8 202.8,-174.1 199.3,-180.1 195.2,-185.6 190.5,-190.6 185.3,-195 179.5,-198.8 173.4,-201.9 166.9,-204.2 160.3,-205.8 153.4,-206.6 146.6,-206.6 139.7,-205.8 133.1,-204.2 126.6,-201.9 120.5,-198.8 114.7,-195 109.5,-190.6 104.8,-185.6 100.7,-180.1 97.2,-174.1 94.5,-167.8 92.5,-161.3 91.3,-154.5 90.9,-147.6 91.3,-140.8 92.5,-134 94.5,-127.4 97.2,-121.1 100.7,-115.2 104.8,-109.7 109.5,-104.7 114.7,-100.3 120.5,-96.5 126.6,-93.4 133.1,-91.1 139.7,-89.5 146.6,-88.7 153.4,-88.7 160.3,-89.5 166.9,-91.1 173.4,-93.4 179.5,-96.5 185.3,-100.3 190.5,-104.7 195.2,-109.7 199.3,-115.2 202.8,-121.1 205.5,-127.4 207.5,-134 208.7,-140.8
  Multi-Layer board cut-out: -90.9,-147.6 -91.3,-154.5 -92.5,-161.3 -94.5,-167.8 -97.2,-174.1 -100.7,-180.1 -104.8,-185.6 -109.5,-190.6 -114.7,-195 -120.5,-198.8 -126.6,-201.9 -133.1,-204.2 -139.7,-205.8 -146.6,-206.6 -153.4,-206.6 -160.3,-205.8 -166.9,-204.2 -173.4,-201.9 -179.5,-198.8 -185.3,-195 -190.5,-190.6 -195.2,-185.6 -199.3,-180.1 -202.8,-174.1 -205.5,-167.8 -207.5,-161.3 -208.7,-154.5 -209.1,-147.6 -208.7,-140.8 -207.5,-134 -205.5,-127.4 -202.8,-121.1 -199.3,-115.2 -195.2,-109.7 -190.5,-104.7 -185.3,-100.3 -179.5,-96.5 -173.4,-93.4 -166.9,-91.1 -160.3,-89.5 -153.4,-88.7 -146.6,-88.7 -139.7,-89.5 -133.1,-91.1 -126.6,-93.4 -120.5,-96.5 -114.7,-100.3 -109.5,-104.7 -104.8,-109.7 -100.7,-115.2 -97.2,-121.1 -94.5,-127.4 -92.5,-134 -91.3,-140.8
  Multi-Layer board cut-out: 209.1,-147.6 208.7,-154.5 207.5,-161.3 205.5,-167.8 202.8,-174.1 199.3,-180.1 195.2,-185.6 190.5,-190.6 185.3,-195 179.5,-198.8 173.4,-201.9 166.9,-204.2 160.3,-205.8 153.4,-206.6 146.6,-206.6 139.7,-205.8 133.1,-204.2 126.6,-201.9 120.5,-198.8 114.7,-195 109.5,-190.6 104.8,-185.6 100.7,-180.1 97.2,-174.1 94.5,-167.8 92.5,-161.3 91.3,-154.5 90.9,-147.6 91.3,-140.8 92.5,-134 94.5,-127.4 97.2,-121.1 100.7,-115.2 104.8,-109.7 109.5,-104.7 114.7,-100.3 120.5,-96.5 126.6,-93.4 133.1,-91.1 139.7,-89.5 146.6,-88.7 153.4,-88.7 160.3,-89.5 166.9,-91.1 173.4,-93.4 179.5,-96.5 185.3,-100.3 190.5,-104.7 195.2,-109.7 199.3,-115.2 202.8,-121.1 205.5,-127.4 207.5,-134 208.7,-140.8
  silkscreen extent -226,-423 226,100
Connector_PinHeader_2.54mm:PinHeader_1x04_P2.54mm_Vertical [mil]
  rect 66.9x66.9 hole 39.4 paste+0 mask+0: 1(0,0)
  round 66.9 hole 39.4 paste+0 mask+0: 2(0,-100) 3(0,-200) 4(0,-300)
  silkscreen extent -52,-352 52,52
CRYSTAL-SMD_4P-L3.2-W2.5-BL [mil]
  rect 55.1x47.2 smd: 1(-43.27,-33.52) 2(43.35,-33.45) 3(43.35,33.45) 4(-43.2,33.45)
  silkscreen extent -89,-75 80,66
CRYSTAL-SMD_4P-L5.0-W3.2-BL [mil]
  rect 63x47.2 smd: 1(-78.7,-47.2) 2(78.7,-47.2) 3(78.7,47.2) 4(-78.7,47.2)
  silkscreen extent -98,-72 98,63
ESOP-10_L4.9-W3.9-P1.00-LS6.2-BL-EP [mil]
  rect 23.6x59.1 smd: 1(-78.7,-108.3) 2(-39.4,-108.3) 3(0,-108.3) 4(39.4,-108.3) 5(78.7,-108.3) 6(78.7,108.3) 7(39.4,108.3) 8(0,108.3) 9(-39.4,108.3) 10(-78.7,108.3)
  rect 110.2x94.5 smd: 11(0,0)
  silkscreen extent -116,-117 98,79
FPC-SMD_4P-P1.00_JS_AFA01-S04FCA-00 [mil]
  rect 13.8x49.2 smd paste+0 mask+2: 1(-59.1,49.7) 2(-19.7,49.7) 3(19.6,49.7) 4(59,49.7)
  rect 78.7x98.4 smd paste+0 mask+2: 5(153.5,-49.7) 6(-153.6,-49.7)
  silkscreen extent -197,-186 197,53
FPC-SMD_6P-P0.50_XUNPU_FPC-05F-6PH20 [mil]
  rect 11.8x49.2 smd paste+0 mask+2: 1(-49.2,50.7) 2(-29.5,50.7) 3(-9.8,50.7) 4(9.9,50.7) 5(29.6,50.7) 6(49.2,50.7)
  rect 78.7x98.4 smd paste+0 mask+2: 7(115.8,-50.7) 8(-115.7,-50.7)
  silkscreen extent -146,-154 146,70
FPC-SMD_12P-P1.00_XUNPU_FPC-1.0FX-12PWBH20 [mil]
  rect 23.6x49.2 smd paste+0 mask+2: 1(-216.6,46.3) 2(-177.2,46.3) 3(-137.8,46.3) 4(-98.5,46.3) 5(-59.1,46.3) 6(-19.7,46.3) 7(19.6,46.3) 8(59,46.3) 9(98.4,46.3) 10(137.8,46.3) 11(177.1,46.3) 12(216.5,46.3)
  rect 78.7x120.1 smd paste+0 mask+2: 13(303.1,-46.2) 14(-303.2,-46.2)
  silkscreen extent -339,-189 338,60
FPC-SMD_17P-P1.00_ZX-1.0FPC-2H-QFX17P [mil]
  rect 11.8x49.2 smd paste+0 mask+2: 1(315,49.7) 2(275.6,49.7) 3(236.2,49.7) 4(196.9,49.7) 5(157.5,49.7) 6(118.1,49.7) 7(78.7,49.7) 8(39.4,49.7) 9(0,49.7) 10(-39.4,49.7) 11(-78.7,49.7) 12(-118.1,49.7) 13(-157.5,49.7) 14(-196.9,49.7) 15(-236.2,49.7) 16(-275.6,49.7) 17(-315,49.7)
  rect 70.9x86.6 smd paste+0 mask+2: 18(-409.4,-49.7) 19(409.4,-49.7)
  silkscreen extent -451,-171 451,81
FPC-SMD_24P-P0.50_FPC-05F-24PH20 [mil]
  rect 11.8x49.2 smd paste+0 mask+2: 1(-226.4,50.7) 2(-206.7,50.7) 3(-187,50.7) 4(-167.3,50.7) 5(-147.6,50.7) 6(-128,50.7) 7(-108.3,50.7) 8(-88.6,50.7) 9(-68.9,50.7) 10(-49.2,50.7) 11(-29.5,50.7) 12(-9.8,50.7) 13(9.8,50.7) 14(29.5,50.7) 15(49.2,50.7) 16(68.9,50.7) 17(88.6,50.7) 18(108.3,50.7) 19(128,50.7) 20(147.6,50.7) 21(167.3,50.7) 22(187,50.7) 23(206.7,50.7) 24(226.4,50.7)
  rect 78.7x98.4 smd paste+0 mask+2: 25(292.9,-50.7) 26(-292.9,-50.7)
  silkscreen extent -320,-180 320,70
IND-SMD_L4.0-W4.0_ANR4012 [mil]
  rect 43.3x145.7 smd: 1(-59,0) 2(59.1,0)
  silkscreen extent -79,-83 79,83
IND-SMD_L7.1-W6.6_H5.0 [mil]
  rect 84.6x130.7 smd: 1(-114.7,0) 2(114.7,0)
  silkscreen extent -130,-130 130,130
L0805 [mil]
  rect 44.6x54.2 smd paste-3937 mask+2: 1(-38,0) 2(38.1,0)
  silkscreen extent -77,-40 73,40
LD:MAX98357_Module [mil]
  round 66.9 hole 39.4 paste+0 mask+0: 1(0,-600) 2(0,-500) 3(0,-400) 4(0,-300) 5(0,-200) 6(0,-100) 7(0,0)
  silkscreen extent -669,-679 79,69
LED0805-RD_YELLOW [mil]
  rect 39.4x49.2 smd: 1(-43.3,0) 2(43.3,0)
  silkscreen extent -83,-37 78,38
LED-SMD_4P-L2.0-W2.0-TL_WS2812B-2020 [mil]
  rect 35.4x27.6 smd: 1(-36.1,21.7) 2(-36.1,-21.6) 3(36,-21.6) 4(36,21.7)
  silkscreen extent -51,-43 39,45
QFN-24_L4.0-W4.0-P0.50-BL-EP2.6 [mil]
  rect 11x26.2 smd paste-3937 mask+2: 1(-49.2,-75.1) 2(-29.5,-75.1) 3(-9.8,-75.1) 4(9.8,-75.1) 5(29.5,-75.1) 6(49.2,-75.1) 13(49.2,75.1) 14(29.5,75.1) 15(9.8,75.1) 16(-9.8,75.1) 17(-29.5,75.1) 18(-49.2,75.1)
  rect 26.2x11 smd paste-3937 mask+2: 7(75.1,-49.2) 8(75.1,-29.5) 9(75.1,-9.8) 10(75.1,9.8) 11(75.1,29.5) 12(75.1,49.2) 19(-75.1,49.2) 20(-75.1,29.5) 21(-75.1,9.8) 22(-75.1,-9.8) 23(-75.1,-29.5) 24(-75.1,-49.2)
  rect 100.4x100.4 smd paste-3937 mask+2: 25(0,0)
  silkscreen extent -82,-100 82,82
R0402 [mil]
  rect 22.3x21.3 smd paste-3937 mask+2: 1(-17,0) 2(17,0)
  silkscreen extent -37,-20 37,20
R0603#1 [mil]
  rect 31.8x34 smd paste-3937 mask+2: 1(-29.7,0) 2(29.7,0)
  silkscreen extent -54,-26 54,26
R0603#2 [mil]
  rect 31.8x34 smd paste-3937 mask+2: 1(-29.6,0) 2(29.7,0)
  silkscreen extent -54,-26 55,26
R0603#3 [mil]
  rect 31.8x34 smd paste-3937 mask+2: 1(-29.7,0) 2(29.6,0)
  silkscreen extent -54,-26 54,26
R0603_1#1 [mil]
  rect 31.8x34 smd paste-3937 mask+2: 1(-29.7,0) 2(29.7,0)
  silkscreen extent -54,-26 54,26
R0603_1#2 [mil]
  rect 31.8x34 smd paste-3937 mask+2: 1(-29.6,0) 2(29.7,0)
  silkscreen extent -54,-26 55,26
R0805#1 [mil]
  rect 44.6x54.2 smd paste-3937 mask+2: 1(-39.4,0) 2(39.3,0)
  silkscreen extent -69,-36 69,36
R0805#2 [mil]
  rect 44.6x54.2 smd paste-3937 mask+2: 1(-39.3,0) 2(39.4,0)
  silkscreen extent -69,-36 69,36
Radxa_rCore_RK3308-bon_1 [mil]
  rect 70.9x27.6 smd paste+0 mask+0: 1(0,-118.1) 2(0,-157.5) 3(0,-196.9) 4(0,-236.2) 5(0,-275.6) 6(0,-315) 7(0,-354.3) 8(0,-393.7) 9(0,-433.1) 10(0,-472.4) 11(0,-511.8) 12(0,-551.2) 13(0,-590.6) 14(0,-629.9) 15(0,-669.3) 16(0,-708.7) 17(0,-748) 18(0,-787.4) 19(0,-826.8) 20(0,-866.1) 21(0,-905.5) 22(0,-944.9) 23(0,-984.3) 24(0,-1023.6) 25(0,-1063) 26(0,-1102.4) 27(0,-1141.7) 28(0,-1181.1) 29(0,-1220.5) 30(0,-1259.8) 61(1378,-1259.8) 62(1378,-1220.5) 63(1378,-1181.1) 64(1378,-1141.7) 65(1378,-1102.4) 66(1378,-1063) 67(1378,-1023.6) 68(1378,-984.3) 69(1378,-944.9) 70(1378,-905.5) 71(1378,-866.1) 72(1378,-826.8) 73(1378,-787.4) 74(1378,-748) 75(1378,-708.7) 76(1378,-669.3) 77(1378,-629.9) 78(1378,-590.6) 79(1378,-551.2) 80(1378,-511.8) 81(1378,-472.4) 82(1378,-433.1) 83(1378,-393.7) 84(1378,-354.3) 85(1378,-315) 86(1378,-275.6) 87(1378,-236.2) 88(1378,-196.9) 89(1378,-157.5) 90(1378,-118.1)
  rect 27.6x70.9 smd paste+0 mask+0: 31(118.1,-1378) 32(157.5,-1378) 33(196.9,-1378) 34(236.2,-1378) 35(275.6,-1378) 36(315,-1378) 37(354.3,-1378) 38(393.7,-1378) 39(433.1,-1378) 40(472.4,-1378) 41(511.8,-1378) 42(551.2,-1378) 43(590.6,-1378) 44(629.9,-1378) 45(669.3,-1378) 46(708.7,-1378) 47(748,-1378) 48(787.4,-1378) 49(826.8,-1378) 50(866.1,-1378) 51(905.5,-1378) 52(944.9,-1378) 53(984.3,-1378) 54(1023.6,-1378) 55(1063,-1378) 56(1102.4,-1378) 57(1141.7,-1378) 58(1181.1,-1378) 59(1220.5,-1378) 60(1259.8,-1378) 91(1259.8,0) 92(1220.5,0) 93(1181.1,0) 94(1141.7,0) 95(1102.4,0) 96(1063,0) 97(1023.6,0) 98(984.3,0) 99(944.9,0) 100(905.5,0) 101(866.1,0) 102(826.8,0) 103(787.4,0) 104(748,0) 105(708.7,0) 106(669.3,0) 107(629.9,0) 108(590.6,0) 109(551.2,0) 110(511.8,0) 111(472.4,0) 112(433.1,0) 113(393.7,0) 114(354.3,0) 115(315,0) 116(275.6,0) 117(236.2,0) 118(196.9,0) 119(157.5,0) 120(118.1,0)
  rect 63x70.9 smd paste+0 mask+0: 121(39.4,-1338.6) 122(1338.6,-1338.6) 123(39.4,-39.4) 124(1338.6,-39.4)
  silkscreen extent -45,-1378 1378,0
RJ45-TH_R-RJ45R08P-C000 [mil]
  round 60 hole 36: 1(140.5,-129.7) 2(100.4,-59.7) 3(60.2,-129.7) 4(20,-59.7) 5(-20.1,-129.7) 6(-60.3,-59.7) 7(-100.4,-129.7) 8(-140.6,-59.7) 9(-270.1,129.7) 10(-180,129.7) 11(179.9,129.7) 12(270,129.7)
  round 98.4 hole 74.8: 13(320,-89.6) 14(-320.1,-89.6)
  Board Outline Layer lines w0.1: 251.8,-294.7 258.9,-294.1 265.9,-292.7 272.7,-290.6 279.3,-287.7 285.5,-284.1 291.3,-279.9 296.5,-275 301.2,-269.6 305.3,-263.8 308.7,-257.5 311.4,-250.8 313.4,-244 314.5,-236.9 314.9,-229.7 314.5,-222.6 313.4,-215.5 311.4,-208.7 308.7,-202 305.3,-195.7 301.2,-189.8 296.5,-184.4 291.3,-179.6 285.5,-175.4 279.3,-171.8 272.7,-168.9 265.9,-166.8 258.9,-165.4 251.8,-164.8 244.6,-165 237.5,-166 230.6,-167.7 223.9,-170.3 217.5,-173.5 211.5,-177.4 206,-182 201,-187.1 196.6,-192.7 192.8,-198.8 189.8,-205.3 187.5,-212.1 185.9,-219.1 185.1,-226.2 185.1,-233.3 185.9,-240.4 187.5,-247.4 189.8,-254.2 192.8,-260.7 196.6,-266.8 201,-272.4 206,-277.5 211.5,-282.1 217.5,-286 223.9,-289.2 230.6,-291.7 237.5,-293.5 244.6,-294.5 251.8,-294.7 ; -248.2,-294.7 -241.1,-294.1 -234.1,-292.7 -227.3,-290.6 -220.7,-287.7 -214.5,-284.1 -208.7,-279.9 -203.5,-275 -198.8,-269.6 -194.7,-263.8 -191.3,-257.5 -188.6,-250.8 -186.6,-244 -185.5,-236.9 -185.1,-229.7 -185.5,-222.6 -186.6,-215.5 -188.6,-208.7 -191.3,-202 -194.7,-195.7 -198.8,-189.8 -203.5,-184.4 -208.7,-179.6 -214.5,-175.4 -220.7,-171.8 -227.3,-168.9 -234.1,-166.8 -241.1,-165.4 -248.2,-164.8 -255.4,-165 -262.5,-166 -269.4,-167.7 -276.1,-170.3 -282.5,-173.5 -288.5,-177.4 -294,-182 -299,-187.1 -303.4,-192.7 -307.2,-198.8 -310.2,-205.3 -312.5,-212.1 -314.1,-219.1 -314.9,-226.2 -314.9,-233.3 -314.1,-240.4 -312.5,-247.4 -310.2,-254.2 -307.2,-260.7 -303.4,-266.8 -299,-272.4 -294,-277.5 -288.5,-282.1 -282.5,-286 -276.1,-289.2 -269.4,-291.7 -262.5,-293.5 -255.4,-294.5 -248.2,-294.7
  Board Outline Layer region: -185.1,-229.7 -185.5,-236.9 -186.6,-244 -188.6,-250.8 -191.3,-257.5 -194.7,-263.8 -198.8,-269.6 -203.5,-275 -208.7,-279.9 -214.5,-284.1 -220.7,-287.7 -227.3,-290.6 -234.1,-292.7 -241.1,-294.1 -248.2,-294.7 -255.4,-294.5 -262.5,-293.5 -269.4,-291.7 -276.1,-289.2 -282.5,-286 -288.5,-282.1 -294,-277.5 -299,-272.4 -303.4,-266.8 -307.2,-260.7 -310.2,-254.2 -312.5,-247.4 -314.1,-240.4 -314.9,-233.3 -314.9,-226.2 -314.1,-219.1 -312.5,-212.1 -310.2,-205.3 -307.2,-198.8 -303.4,-192.7 -299,-187.1 -294,-182 -288.5,-177.4 -282.5,-173.5 -276.1,-170.3 -269.4,-167.7 -262.5,-166 -255.4,-165 -248.2,-164.8 -241.1,-165.4 -234.1,-166.8 -227.3,-168.9 -220.7,-171.8 -214.5,-175.4 -208.7,-179.6 -203.5,-184.4 -198.8,-189.8 -194.7,-195.7 -191.3,-202 -188.6,-208.7 -186.6,-215.5 -185.5,-222.6
  Board Outline Layer region: -185.1,-229.7 -185.5,-236.9 -186.6,-244 -188.6,-250.8 -191.3,-257.5 -194.7,-263.8 -198.8,-269.6 -203.5,-275 -208.7,-279.9 -214.5,-284.1 -220.7,-287.7 -227.3,-290.6 -234.1,-292.7 -241.1,-294.1 -248.2,-294.7 -255.4,-294.5 -262.5,-293.5 -269.4,-291.7 -276.1,-289.2 -282.5,-286 -288.5,-282.1 -294,-277.5 -299,-272.4 -303.4,-266.8 -307.2,-260.7 -310.2,-254.2 -312.5,-247.4 -314.1,-240.4 -314.9,-233.3 -314.9,-226.2 -314.1,-219.1 -312.5,-212.1 -310.2,-205.3 -307.2,-198.8 -303.4,-192.7 -299,-187.1 -294,-182 -288.5,-177.4 -282.5,-173.5 -276.1,-170.3 -269.4,-167.7 -262.5,-166 -255.4,-165 -248.2,-164.8 -241.1,-165.4 -234.1,-166.8 -227.3,-168.9 -220.7,-171.8 -214.5,-175.4 -208.7,-179.6 -203.5,-184.4 -198.8,-189.8 -194.7,-195.7 -191.3,-202 -188.6,-208.7 -186.6,-215.5 -185.5,-222.6
  Board Outline Layer region: 314.9,-229.7 314.5,-236.9 313.4,-244 311.4,-250.8 308.7,-257.5 305.3,-263.8 301.2,-269.6 296.5,-275 291.3,-279.9 285.5,-284.1 279.3,-287.7 272.7,-290.6 265.9,-292.7 258.9,-294.1 251.8,-294.7 244.6,-294.5 237.5,-293.5 230.6,-291.7 223.9,-289.2 217.5,-286 211.5,-282.1 206,-277.5 201,-272.4 196.6,-266.8 192.8,-260.7 189.8,-254.2 187.5,-247.4 185.9,-240.4 185.1,-233.3 185.1,-226.2 185.9,-219.1 187.5,-212.1 189.8,-205.3 192.8,-198.8 196.6,-192.7 201,-187.1 206,-182 211.5,-177.4 217.5,-173.5 223.9,-170.3 230.6,-167.7 237.5,-166 244.6,-165 251.8,-164.8 258.9,-165.4 265.9,-166.8 272.7,-168.9 279.3,-171.8 285.5,-175.4 291.3,-179.6 296.5,-184.4 301.2,-189.8 305.3,-195.7 308.7,-202 311.4,-208.7 313.4,-215.5 314.5,-222.6
  Board Outline Layer region: 314.9,-229.7 314.5,-236.9 313.4,-244 311.4,-250.8 308.7,-257.5 305.3,-263.8 301.2,-269.6 296.5,-275 291.3,-279.9 285.5,-284.1 279.3,-287.7 272.7,-290.6 265.9,-292.7 258.9,-294.1 251.8,-294.7 244.6,-294.5 237.5,-293.5 230.6,-291.7 223.9,-289.2 217.5,-286 211.5,-282.1 206,-277.5 201,-272.4 196.6,-266.8 192.8,-260.7 189.8,-254.2 187.5,-247.4 185.9,-240.4 185.1,-233.3 185.1,-226.2 185.9,-219.1 187.5,-212.1 189.8,-205.3 192.8,-198.8 196.6,-192.7 201,-187.1 206,-182 211.5,-177.4 217.5,-173.5 223.9,-170.3 230.6,-167.7 237.5,-166 244.6,-165 251.8,-164.8 258.9,-165.4 265.9,-166.8 272.7,-168.9 279.3,-171.8 285.5,-175.4 291.3,-179.6 296.5,-184.4 301.2,-189.8 305.3,-195.7 308.7,-202 311.4,-208.7 313.4,-215.5 314.5,-222.6
  Multi-Layer board cut-out: -185.1,-229.7 -185.5,-236.9 -186.6,-244 -188.6,-250.8 -191.3,-257.5 -194.7,-263.8 -198.8,-269.6 -203.5,-275 -208.7,-279.9 -214.5,-284.1 -220.7,-287.7 -227.3,-290.6 -234.1,-292.7 -241.1,-294.1 -248.2,-294.7 -255.4,-294.5 -262.5,-293.5 -269.4,-291.7 -276.1,-289.2 -282.5,-286 -288.5,-282.1 -294,-277.5 -299,-272.4 -303.4,-266.8 -307.2,-260.7 -310.2,-254.2 -312.5,-247.4 -314.1,-240.4 -314.9,-233.3 -314.9,-226.2 -314.1,-219.1 -312.5,-212.1 -310.2,-205.3 -307.2,-198.8 -303.4,-192.7 -299,-187.1 -294,-182 -288.5,-177.4 -282.5,-173.5 -276.1,-170.3 -269.4,-167.7 -262.5,-166 -255.4,-165 -248.2,-164.8 -241.1,-165.4 -234.1,-166.8 -227.3,-168.9 -220.7,-171.8 -214.5,-175.4 -208.7,-179.6 -203.5,-184.4 -198.8,-189.8 -194.7,-195.7 -191.3,-202 -188.6,-208.7 -186.6,-215.5 -185.5,-222.6
  Multi-Layer board cut-out: 314.9,-229.7 314.5,-236.9 313.4,-244 311.4,-250.8 308.7,-257.5 305.3,-263.8 301.2,-269.6 296.5,-275 291.3,-279.9 285.5,-284.1 279.3,-287.7 272.7,-290.6 265.9,-292.7 258.9,-294.1 251.8,-294.7 244.6,-294.5 237.5,-293.5 230.6,-291.7 223.9,-289.2 217.5,-286 211.5,-282.1 206,-277.5 201,-272.4 196.6,-266.8 192.8,-260.7 189.8,-254.2 187.5,-247.4 185.9,-240.4 185.1,-233.3 185.1,-226.2 185.9,-219.1 187.5,-212.1 189.8,-205.3 192.8,-198.8 196.6,-192.7 201,-187.1 206,-182 211.5,-177.4 217.5,-173.5 223.9,-170.3 230.6,-167.7 237.5,-166 244.6,-165 251.8,-164.8 258.9,-165.4 265.9,-166.8 272.7,-168.9 279.3,-171.8 285.5,-175.4 291.3,-179.6 296.5,-184.4 301.2,-189.8 305.3,-195.7 308.7,-202 311.4,-208.7 313.4,-215.5 314.5,-222.6
  silkscreen extent -320,-445 320,180
SO-16_L10.3-W7.5-P1.27-LS10.3-BL [mil]
  rect 25x85 smd: 1(-175,-189) 2(-125,-189) 3(-75,-189) 4(-25,-189) 5(25,-189) 6(75,-189) 7(125,-189) 8(175,-189) 9(175,189) 10(125,189) 11(75,189) 12(25,189) 13(-25,189) 14(-75,189) 15(-125,189) 16(-175,189)
  silkscreen extent -204,-134 205,135
SOD-123_L2.7-W1.6-LS3.7-RD-1#1 [mil]
  rect 47.2x37.4 smd: 1(-66.9,0) 2(66.9,0)
  silkscreen extent -71,-39 53,38
SOD-123_L2.7-W1.6-LS3.7-RD-1#2 [mil]
  rect 47.2x37.4 smd: 1(-66.9,0) 2(67,0)
  silkscreen extent -71,-39 53,38
SOT-23-3_L3.0-W1.7-P0.95-LS2.9-BR#1 [mil]
  rect 40.8x20.9 smd: 1(43.3,-37.4) 2(43.3,37.4) 3(-43.4,0)
  silkscreen extent -34,-60 34,60
SOT-23-3_L3.0-W1.7-P0.95-LS2.9-BR#2 [mil]
  rect 40.8x20.9 smd: 1(43.4,-37.4) 2(43.4,37.4) 3(-43.4,0)
  silkscreen extent -34,-60 34,60
SOT-23-5_L3.0-W1.7-P0.95-LS2.8-BL [mil]
  rect 19.3x45.6 smd: 1(-37.4,-45.4) 2(0,-45.4) 3(37.4,-45.4)
  rect 19.3x46.3 smd: 4(37.4,45.4) 5(-37.4,45.4)
  silkscreen extent -71,-51 60,34
SOT-323-3_L2.0-W1.3-P1.30-LS2.1-BR [mil]
  rect 36.9x19.7 smd: 1(35.3,-25.6) 2(35.3,25.6) 3(-35.4,0)
  silkscreen extent -28,-44 28,44
SSOP-28_L9.9-W3.9-P0.635-LS6.0-BL-1 [mil]
  rect 13.8x68.9 smd: 1(-162.5,-103.3) 2(-137.5,-103.3) 3(-112.5,-103.3) 4(-87.5,-103.3) 5(-62.5,-103.3) 6(-37.5,-103.3) 7(-12.5,-103.3) 8(12.5,-103.3) 9(37.5,-103.3) 10(62.5,-103.3) 11(87.5,-103.3) 12(112.5,-103.3) 13(137.5,-103.3) 14(162.5,-103.3) 15(162.5,103.4) 16(137.5,103.4) 17(112.5,103.4) 18(87.5,103.4) 19(62.5,103.4) 20(37.5,103.4) 21(12.5,103.4) 22(-12.5,103.4) 23(-37.5,103.4) 24(-62.5,103.4) 25(-87.5,103.4) 26(-112.5,103.4) 27(-137.5,103.4) 28(-162.5,103.4)
  silkscreen extent -222,-107 195,77
SW-SMD_HX-TS-1101-C-W [mil]
  rect 43.3x43.3 smd: 1(-143.7,0) 2(143.7,0)
  silkscreen extent -122,-70 125,71
Test-Point-0.5mm#1 [mil]
  round 48.6 smd: 1(0,0)
Test-Point-0.5mm#2 [mil]
  round 39.4 smd: 1(0,0)
TF-SMD_TF-025 [mil]
  rect 23.6x51.2 smd: 1(151.2,-232.3) 2(107.9,-232.3) 3(64.6,-232.3) 4(21.5,-232.3) 5(-22,-232.3) 6(-65.3,-232.3) 7(-108.6,-232.3) 8(-151.9,-232.3)
  rect 59.1x94.5 smd: 9(-200.8,122) 9(200.8,122)
  silkscreen extent -222,-173 272,146
TF-SMD_TF-PUSH [mil]
  rect 27.6x63 smd: 1(88.6,208.7) 2(45.3,208.7) 3(2,208.7) 4(-41.3,208.7) 5(-84.6,208.7) 6(-127.9,208.7) 7(-171.3,208.7) 8(-214.6,208.7) CD(-257.9,208.7)
  rect 47.2x59.1 smd: 10(-305.1,169.3)
  rect 47.2x86.6 smd: 11(-305.1,-208.7) 12(305.1,-208.7)
  rect 63x59.1 smd: 13(269.7,169.3)
  Board Outline Layer lines w0.1: 119,-248 123.3,-247.8 127.4,-246.9 131.3,-245.2 134.8,-242.9 137.9,-240 140.4,-236.5 142.2,-232.7 143.3,-228.6 143.7,-224.4 143.3,-220.2 142.2,-216.1 140.4,-212.3 137.9,-208.9 134.8,-205.9 131.3,-203.6 127.4,-201.9 123.3,-201 119,-200.8 114.8,-201.4 110.8,-202.7 107.1,-204.7 103.8,-207.3 101,-210.5 98.8,-214.2 97.3,-218.1 96.6,-222.3 96.6,-226.5 97.3,-230.7 98.8,-234.7 101,-238.3 103.8,-241.5 107.1,-244.1 110.8,-246.1 114.8,-247.4 119,-248 ; -195.9,-248 -191.7,-247.8 -187.6,-246.9 -183.7,-245.2 -180.2,-242.9 -177.1,-240 -174.6,-236.5 -172.8,-232.7 -171.6,-228.6 -171.3,-224.4 -171.6,-220.2 -172.8,-216.1 -174.6,-212.3 -177.1,-208.9 -180.2,-205.9 -183.7,-203.6 -187.6,-201.9 -191.7,-201 -195.9,-200.8 -200.1,-201.4 -204.2,-202.7 -207.9,-204.7 -211.2,-207.3 -214,-210.5 -216.2,-214.2 -217.7,-218.1 -218.4,-222.3 -218.4,-226.5 -217.7,-230.7 -216.2,-234.7 -214,-238.3 -211.2,-241.5 -207.9,-244.1 -204.2,-246.1 -200.1,-247.4 -195.9,-248
  Board Outline Layer region: -171.3,-224.4 -171.6,-228.6 -172.8,-232.7 -174.6,-236.5 -177.1,-240 -180.2,-242.9 -183.7,-245.2 -187.6,-246.9 -191.7,-247.8 -195.9,-248 -200.1,-247.4 -204.2,-246.1 -207.9,-244.1 -211.2,-241.5 -214,-238.3 -216.2,-234.7 -217.7,-230.7 -218.4,-226.5 -218.4,-222.3 -217.7,-218.1 -216.2,-214.2 -214,-210.5 -211.2,-207.3 -207.9,-204.7 -204.2,-202.7 -200.1,-201.4 -195.9,-200.8 -191.7,-201 -187.6,-201.9 -183.7,-203.6 -180.2,-205.9 -177.1,-208.9 -174.6,-212.3 -172.8,-216.1 -171.6,-220.2
  Board Outline Layer region: -171.3,-224.4 -171.6,-228.6 -172.8,-232.7 -174.6,-236.5 -177.1,-240 -180.2,-242.9 -183.7,-245.2 -187.6,-246.9 -191.7,-247.8 -195.9,-248 -200.1,-247.4 -204.2,-246.1 -207.9,-244.1 -211.2,-241.5 -214,-238.3 -216.2,-234.7 -217.7,-230.7 -218.4,-226.5 -218.4,-222.3 -217.7,-218.1 -216.2,-214.2 -214,-210.5 -211.2,-207.3 -207.9,-204.7 -204.2,-202.7 -200.1,-201.4 -195.9,-200.8 -191.7,-201 -187.6,-201.9 -183.7,-203.6 -180.2,-205.9 -177.1,-208.9 -174.6,-212.3 -172.8,-216.1 -171.6,-220.2
  Board Outline Layer region: 143.7,-224.4 143.3,-228.6 142.2,-232.7 140.4,-236.5 137.9,-240 134.8,-242.9 131.3,-245.2 127.4,-246.9 123.3,-247.8 119,-248 114.8,-247.4 110.8,-246.1 107.1,-244.1 103.8,-241.5 101,-238.3 98.8,-234.7 97.3,-230.7 96.6,-226.5 96.6,-222.3 97.3,-218.1 98.8,-214.2 101,-210.5 103.8,-207.3 107.1,-204.7 110.8,-202.7 114.8,-201.4 119,-200.8 123.3,-201 127.4,-201.9 131.3,-203.6 134.8,-205.9 137.9,-208.9 140.4,-212.3 142.2,-216.1 143.3,-220.2
  Board Outline Layer region: 143.7,-224.4 143.3,-228.6 142.2,-232.7 140.4,-236.5 137.9,-240 134.8,-242.9 131.3,-245.2 127.4,-246.9 123.3,-247.8 119,-248 114.8,-247.4 110.8,-246.1 107.1,-244.1 103.8,-241.5 101,-238.3 98.8,-234.7 97.3,-230.7 96.6,-226.5 96.6,-222.3 97.3,-218.1 98.8,-214.2 101,-210.5 103.8,-207.3 107.1,-204.7 110.8,-202.7 114.8,-201.4 119,-200.8 123.3,-201 127.4,-201.9 131.3,-203.6 134.8,-205.9 137.9,-208.9 140.4,-212.3 142.2,-216.1 143.3,-220.2
  Multi-Layer board cut-out: -171.3,-224.4 -171.6,-228.6 -172.8,-232.7 -174.6,-236.5 -177.1,-240 -180.2,-242.9 -183.7,-245.2 -187.6,-246.9 -191.7,-247.8 -195.9,-248 -200.1,-247.4 -204.2,-246.1 -207.9,-244.1 -211.2,-241.5 -214,-238.3 -216.2,-234.7 -217.7,-230.7 -218.4,-226.5 -218.4,-222.3 -217.7,-218.1 -216.2,-214.2 -214,-210.5 -211.2,-207.3 -207.9,-204.7 -204.2,-202.7 -200.1,-201.4 -195.9,-200.8 -191.7,-201 -187.6,-201.9 -183.7,-203.6 -180.2,-205.9 -177.1,-208.9 -174.6,-212.3 -172.8,-216.1 -171.6,-220.2
  Multi-Layer board cut-out: 143.7,-224.4 143.3,-228.6 142.2,-232.7 140.4,-236.5 137.9,-240 134.8,-242.9 131.3,-245.2 127.4,-246.9 123.3,-247.8 119,-248 114.8,-247.4 110.8,-246.1 107.1,-244.1 103.8,-241.5 101,-238.3 98.8,-234.7 97.3,-230.7 96.6,-226.5 96.6,-222.3 97.3,-218.1 98.8,-214.2 101,-210.5 103.8,-207.3 107.1,-204.7 110.8,-202.7 114.8,-201.4 119,-200.8 123.3,-201 127.4,-201.9 131.3,-203.6 134.8,-205.9 137.9,-208.9 140.4,-212.3 142.2,-216.1 143.3,-220.2
  silkscreen extent -286,-382 315,209
TSOT23-8 [mil]
  rect 11.8x50 smd paste+0 mask+4: 1(-38.4,-51.2) 2(-12.8,-51.2) 3(12.8,-51.2) 4(38.4,-51.2) 5(38.4,51.2) 6(12.8,51.2) 7(-12.8,51.2) 8(-38.4,51.2)
  silkscreen extent -80,-50 59,32
TSOT-23-3_L3.0-W1.6-P0.95-LS2.8-BR#1 [mil]
  rect 42.2x27.6 smd: 1(44.7,-37.4) 2(44.7,37.4) 3(-44.8,0)
  silkscreen extent -35,-62 35,62
TSOT-23-3_L3.0-W1.6-P0.95-LS2.8-BR#2 [mil]
  rect 42.2x27.6 smd: 1(44.7,-37.4) 2(44.7,37.4) 3(-44.7,0)
  silkscreen extent -34,-62 34,62
TYPE-C-SMD_UC.01.51-11-0017 [mil]
  rect 23.6x44.1 smd paste-3937 mask+2: A1B12(-125.9,89.6) A4B9(-94.4,89.6) B1A12(126,89.6) B4A9(94.5,89.6)
  rect 11.8x44.1 smd paste-3937 mask+2: A5(-49.2,89.6) A6(-9.8,89.6) A7(9.9,89.6) A8(49.3,89.6) B5(68.9,89.6) B6(29.6,89.6) B7(-29.5,89.6) B8(-68.9,89.6)
  oval 39.4x86.6 hole 23.6 slot 70.9 at 90 deg: EH1(-170,-89.7) EH1(170.1,-89.7)
  oval 39.4x70.9 hole 23.6 slot 55.1 at 90 deg: EH1(-170,67.8) EH1(170.1,67.8)
  silkscreen extent -176,-161 176,24
USB-A-TH_UE27AC54100 [mil]
  round 55.1 hole 36.2: 1(-137.5,53.5) 2(-39.1,53.5) 3(39.7,53.5) 4(138.1,53.5)
  round 126 hole 90.6: 5(-258.7,-53.5) 5(258.7,-53.5)
  silkscreen extent -285,-460 286,93
WIFIM-SMD_38P-L19.2-W18.0-P1.27 [mil]
  rect 37.4x82.7 smd: 1(356.1,354.3) 2(306.1,354.3) 3(256.1,354.3) 4(206.1,354.3) 5(156.1,354.3) 6(106.1,354.3) 7(56.1,354.3) 8(6.1,354.3) 9(-43.9,354.3) 10(-93.9,354.3) 11(-143.9,354.3) 12(-193.9,354.3) 13(-243.9,354.3) 14(-293.9,354.3) 25(-293.9,-354.3) 26(-243.9,-354.3) 27(-193.9,-354.3) 28(-143.9,-354.3) 29(-93.9,-354.3) 30(-43.9,-354.3) 31(6.1,-354.3) 32(56.1,-354.3) 33(106.1,-354.3) 34(156.1,-354.3) 35(206.1,-354.3) 36(256.1,-354.3) 37(306.1,-354.3) 38(356.1,-354.3)
  rect 82.7x37.4 smd: 15(-356.1,225) 16(-356.1,175) 17(-356.1,125) 18(-356.1,75) 19(-356.1,25) 20(-356.1,-25) 21(-356.1,-75) 22(-356.1,-125) 23(-356.1,-175) 24(-356.1,-225)
  rect 149.6x149.6 smd: 39(52,59.4)
  silkscreen extent -353,-354 415,414
XFMR-SMD_16P-L12.7-W7.1-P1.27-LS9.4-BL [mil]
  oval 26.5x84.5 smd: 1(-175,-165.5) 2(-125,-165.5) 3(-75,-165.5) 4(-25,-165.5) 5(25,-165.5) 6(75,-165.5) 7(125,-165.5) 8(175,-165.5) 9(175,165.5) 10(125,165.5) 11(75,165.5) 12(25,165.5) 13(-25,165.5) 14(-75,165.5) 15(-125,165.5) 16(-175,165.5)
  silkscreen extent -250,-166 250,140

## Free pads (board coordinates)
  round 39.4 smd far side: 1(5780,4980) 1(5840,4950) 1(6110,4430) 1(6140,4370) GND(6744.2,4733.3)

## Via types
v1: diameter 24, hole 12, Top Layer to Bottom Layer, 576 vias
